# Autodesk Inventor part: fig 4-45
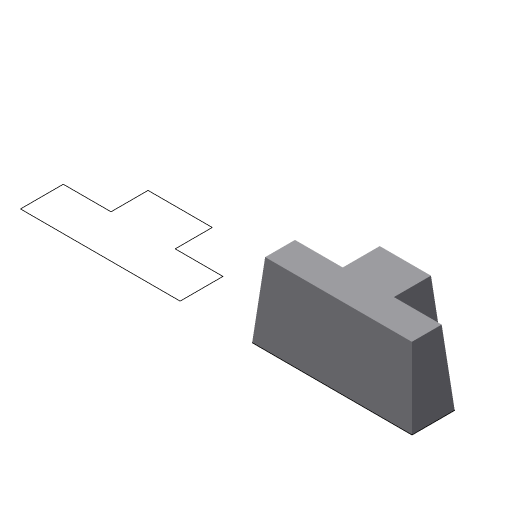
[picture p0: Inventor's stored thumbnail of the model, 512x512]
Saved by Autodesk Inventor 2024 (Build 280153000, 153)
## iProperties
Created: 2004-05
Part Number: fig 4-45
Document SubType Name: Modeling
Designer: CADCIM Technologies
Manufacturer: Standard
Standards Organization: Custom
Density: 1 g/cm^3
Material: Generic
Appearance: Default
Author: CADCIM Technologies
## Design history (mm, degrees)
sketch "Sketch1"
  geometry: L1 (31.783, 34.561)-(31.783, 22.933); L2 (31.783, 22.933)-(16.796, 22.933); L3 (16.796, 22.933)-(16.796, 9.496); L4 (16.796, 9.496)-(66.925, 9.496); L5 (66.925, 9.496)-(66.925, 22.933); L6 (66.925, 22.933)-(51.938, 22.933); L7 (51.938, 22.933)-(51.938, 34.561); L8 (51.938, 34.561)-(31.783, 34.561); L9 (-41.013, 34.561)-(-41.013, 22.933); L10 (-41.013, 22.933)-(-56, 22.933); L11 (-56, 22.933)-(-56, 9.496); L12 (-56, 9.496)-(-5.871, 9.496); L13 (-5.871, 9.496)-(-5.871, 22.933); L14 (-5.871, 22.933)-(-20.858, 22.933); L15 (-20.858, 22.933)-(-20.858, 34.561); L16 (-20.858, 34.561)-(-41.013, 34.561)
  constraints: 32 end point, 10 parallel, 4 equal length, 2 collinear, 2 perpendicular, 2 vertical
extrude "Extrusion1" new body sketch "Sketch1" distance "d0" = 23.25; taper "d1" = -5 deg
body "Solid1"
